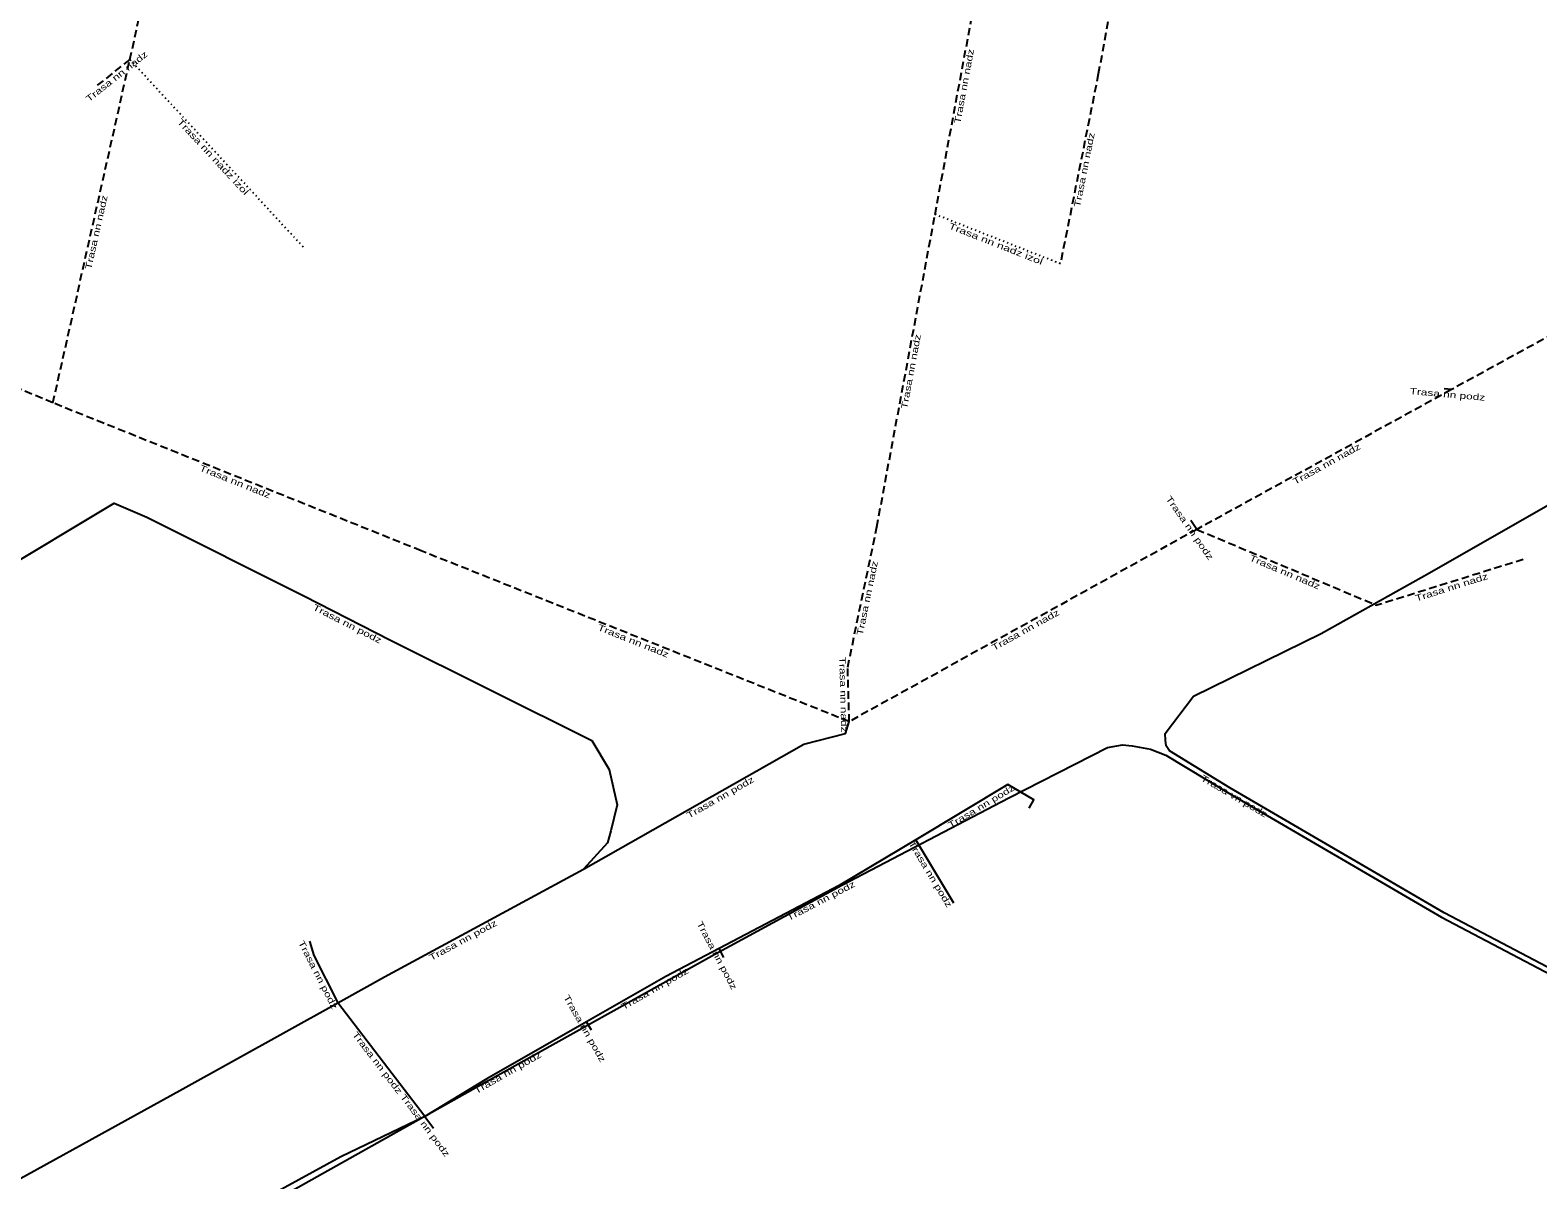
# Model space of a CAD drawing. Extents: x -733620 to -732615, y -1025255 to -1024617.
# Drawn here: x -733235.2 to -733116.1, y -1024903.7 to -1024812.8 of the extents above; entities that cross this region are included whole.
import ezdxf
from ezdxf.enums import TextEntityAlignment as Align

# ---------------------------------------------------------------- set-up
doc = ezdxf.new("R2010")
doc.units = 0
doc.header["$LTSCALE"] = 0.2
doc.linetypes.add('DOTTED', pattern=[1.5, 0.3, -1.2])
doc.linetypes.add('MEDIUM_DASHED', pattern=[4.5, 3, -1.5])
doc.layers.add('11', color=7, linetype='MEDIUM_DASHED', lineweight=25)
doc.layers.add('21', color=7, linetype='Continuous', lineweight=25)
doc.layers.add('20', color=7, linetype='Continuous')

msp = doc.modelspace()

# ---------------------------------------------------------------- linework, layer by layer
at = {"layer": '11'}
for p, q in [((-733147.6, -1024798.9), (-733150.8, -1024816.3)), ((-733163.7, -1024827.4), (-733159.9, -1024807)), ((-733233.4, -1024842.3), (-733227.32, -1024815.16)), ((-733227.32, -1024815.16), (-733229.9, -1024817.2)), ((-733150.8, -1024816.3), (-733153.8, -1024831.3)), ((-733168.3, -1024852.1), (-733163.7, -1024827.4)), ((-733099.83, -1024828.62), (-733122.89, -1024841.25)), ((-733233.4, -1024842.3), (-733262.4, -1024830.2)), ((-733122.89, -1024841.25), (-733143.01, -1024852.3)), ((-733204.31, -1024853.99), (-733233.4, -1024842.3)), ((-733170.6, -1024863.2), (-733168.3, -1024852.1)), ((-733143.01, -1024852.3), (-733170.48, -1024867.49)), ((-733143.01, -1024852.3), (-733128.8, -1024858.3)), ((-733170.48, -1024867.49), (-733204.31, -1024853.99)), ((-733117.22, -1024854.67), (-733128.8, -1024858.3)), ((-733170.48, -1024867.49), (-733170.6, -1024863.2))]:
    msp.add_line(p, q, dxfattribs=at)
at = {"layer": '11', "linetype": 'DOTTED'}
for p, q in [((-733227.32, -1024815.16), (-733213.6, -1024830)), ((-733153.8, -1024831.3), (-733163.7, -1024827.4))]:
    msp.add_line(p, q, dxfattribs=at)
at = {"layer": '11', "linetype": 'Continuous'}
for p, q in [((-733122.89, -1024841.25), (-733123.46, -1024841.2)), ((-733143.01, -1024852.3), (-733143.5, -1024851.6)), ((-733162.22, -1024881.85), (-733165.23, -1024876.83)), ((-733180.4, -1024886.13), (-733180.77, -1024885.43)), ((-733204.02, -1024898.7), (-733210.88, -1024889.72)), ((-733190.85, -1024891.88), (-733191.23, -1024891.21)), ((-733204.02, -1024898.7), (-733203.33, -1024899.62))]:
    msp.add_line(p, q, dxfattribs=at)
at = {"layer": '11'}
msp.add_lwpolyline([(-733227.32, -1024815.16), (-733220.46, -1024784.35), (-733210.9, -1024795.6)], dxfattribs=at)
at = {"layer": '11', "linetype": 'Continuous'}
for points in [[(-733238.99, -1024856.39), (-733238.15, -1024855.97), (-733228.55, -1024850.23), (-733225.98, -1024851.32), (-733213.53, -1024857.58), (-733206.78, -1024861.02), (-733190.83, -1024868.98), (-733189.45, -1024871.27), (-733188.81, -1024874.06), (-733189.33, -1024876.13), (-733189.59, -1024877.07), (-733191.48, -1024879.15)], [(-733191.48, -1024879.15), (-733174.08, -1024869.28), (-733170.763, -1024868.432), (-733170.48, -1024867.49)], [(-733156.27, -1024874.33), (-733155.9, -1024873.68), (-733157.96, -1024872.47), (-733165.23, -1024876.83)], [(-733165.23, -1024876.83), (-733171.28, -1024880.45), (-733180.77, -1024885.43)], [(-733210.88, -1024889.72), (-733207.19, -1024887.67), (-733191.48, -1024879.15)], [(-733213.13, -1024884.84), (-733212.78, -1024885.98), (-733210.88, -1024889.72)], [(-733180.77, -1024885.43), (-733184.98, -1024887.64), (-733191.23, -1024891.21)], [(-733281.31, -1024929.64), (-733260.86, -1024917.5), (-733241.06, -1024906.39), (-733223.38, -1024896.65), (-733210.88, -1024889.72)], [(-733191.23, -1024891.21), (-733199.12, -1024895.72), (-733204.02, -1024898.7)], [(-733204.02, -1024898.7), (-733210.64, -1024901.9), (-733224.74, -1024909.6), (-733225.77, -1024910.63), (-733232.35, -1024917.9)]]:
    msp.add_lwpolyline(points, dxfattribs=at)
at = {"layer": '21'}
for points in [[(-733096.073, -1024897.023), (-733123.483, -1024882.599), (-733140.41, -1024872.717), (-733145.166, -1024869.804), (-733145.435, -1024869.406), (-733145.504, -1024868.954), (-733145.52, -1024868.441), (-733143.276, -1024865.48), (-733133.188, -1024860.519), (-733124.635, -1024855.725), (-733102.986, -1024843.362)], [(-733232.093, -1024918.419), (-733231.922, -1024918.221), (-733225.506, -1024910.855), (-733225.47, -1024910.717), (-733199.151, -1024895.947), (-733181.112, -1024885.859), (-733171.072, -1024880.413), (-733157.87, -1024873.505), (-733150.085, -1024869.53), (-733148.899, -1024869.333), (-733148.113, -1024869.41), (-733146.681, -1024869.668), (-733145.467, -1024870.133), (-733140.616, -1024873.061), (-733123.677, -1024882.949), (-733096.243, -1024897.385)]]:
    msp.add_lwpolyline(points, dxfattribs=at)

# ---------------------------------------------------------------- texts
at = {"layer": '20'}
for s, rotation, width, p in [('Trasa nn nadz', 38.333, 1.4, (-733228.2066, -1024816.6896)), ('Trasa nn nadz', 79.448, 1.4, (-733161.1603, -1024817.3183)), ('Trasa nn nadz izol', 312.754, 1.45, (-733220.9371, -1024823.0208)), ('Trasa nn nadz', 78.69, 1.4, (-733151.6625, -1024823.9265)), ('Trasa nn nadz', 77.373, 1.4, (-733229.7257, -1024828.8712)), ('Trasa nn nadz izol', 338.499, 1.45, (-733158.9881, -1024829.9538)), ('Trasa nn nadz', 79.45, 1.4, (-733165.3604, -1024839.8683)), ('Trasa nn podz', 354.987, 1.4, (-733123.2313, -1024841.8717)), ('Trasa nn nadz', 28.776, 1.4, (-733132.6358, -1024847.3449)), ('Trasa nn nadz', 338.107, 1.4, (-733219.0967, -1024848.7473)), ('Trasa nn podz', 304.992, 1.4, (-733143.7874, -1024852.3221)), ('Trasa nn nadz', 78.294, 1.4, (-733168.8133, -1024857.7812)), ('Trasa nn nadz', 337.109, 1.4, (-733136.1577, -1024855.8979)), ('Trasa nn nadz', 17.405, 1.4, (-733122.8143, -1024857.1047)), ('Trasa nn podz', 332.995, 1.4, (-733210.258, -1024859.9765)), ('Trasa nn nadz', 28.941, 1.4, (-733156.4295, -1024860.4631)), ('Trasa nn nadz', 338.245, 1.4, (-733187.6352, -1024861.3442)), ('Trasa nn nadz', 271.602, 1.4, (-733171.1891, -1024865.3625)), ('Trasa nn podz', 29.564, 1.4, (-733180.5418, -1024873.6931)), ('Trasa vn podz', 329.724, 1.4, (-733140.1905, -1024873.5977)), ('Trasa nn podz', 30.952, 1.4, (-733159.9151, -1024874.4002)), ('Trasa nn podz', 300.947, 1.4, (-733164.2815, -1024879.6739)), ('Trasa nn podz', 27.689, 1.4, (-733172.6017, -1024881.8774)), ('Trasa nn podz', 28.472, 1.4, (-733200.8807, -1024884.9874)), ('Trasa nn podz', 297.86, 1.4, (-733181.1597, -1024886.0837)), ('Trasa nn podz', 296.932, 1.4, (-733212.6794, -1024887.6123)), ('Trasa nn podz', 29.735, 1.4, (-733185.7175, -1024888.8099)), ('Trasa nn podz', 299.56, 1.4, (-733191.6053, -1024891.8642)), ('Trasa nn podz', 307.377, 1.4, (-733207.9659, -1024894.6037)), ('Trasa nn podz', 29.753, 1.4, (-733197.3416, -1024895.4518)), ('Trasa nn podz', 306.87, 1.4, (-733204.1951, -1024899.5495))]:
    msp.add_text(s, height=0.5, rotation=rotation, dxfattribs=dict(at, width=width)).set_placement(p, align=Align.CENTER)

doc.saveas('drawing.dxf')
